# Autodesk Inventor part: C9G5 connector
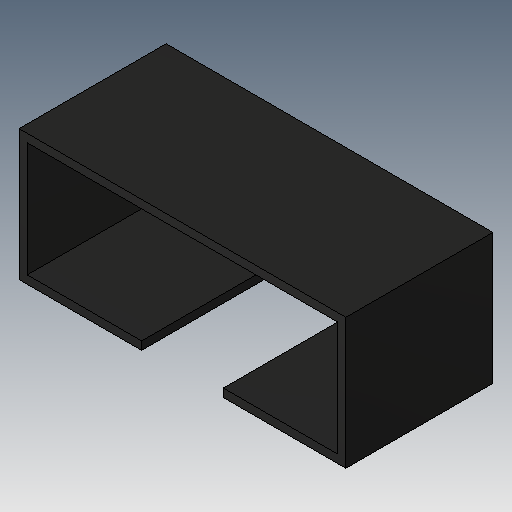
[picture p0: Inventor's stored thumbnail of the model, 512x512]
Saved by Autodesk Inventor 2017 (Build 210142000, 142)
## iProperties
Created: 2005-12
Part Number: C9G5 connector
Material: Generic
Document SubType Name: Modeling
Designer: DanielSeverino
Density: 1 g/cm^3
Appearance: Default
Author: DanielSeverino
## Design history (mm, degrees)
feature "Solid1"
body "Solid2"
